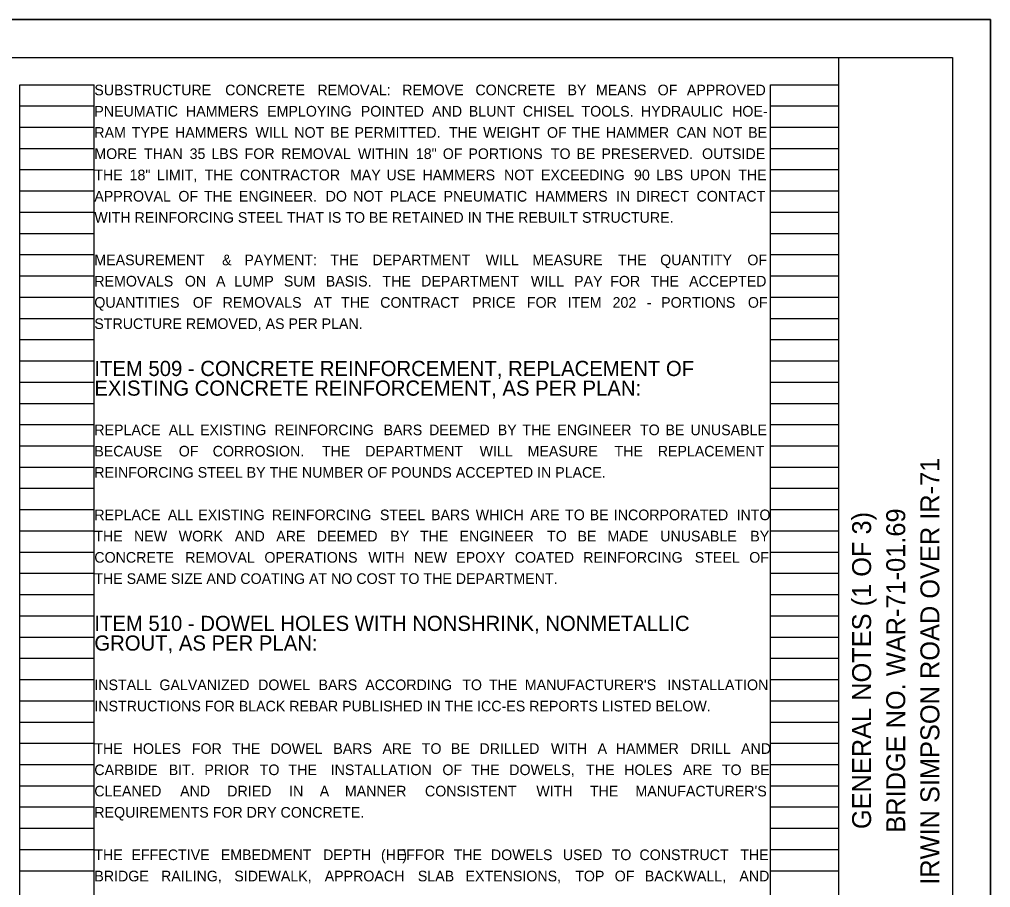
# Model space of a CAD drawing. Extents: x 0 to 34, y 0 to 22.
# Drawn here: x 21.2 to 34, y 10.56 to 22 of the extents above; entities that cross this region are included whole.
import ezdxf

# ---------------------------------------------------------------- set-up
doc = ezdxf.new("R2010")
doc.units = 0
for name, color, linetype in [('BR_P_Gen_Text', 7, 'Continuous'), ('Default', 7, 'Continuous'), ('SC_Scratch1', 7, 'Continuous'), ('SH_Border', 7, 'Continuous'), ('SH_Cut_Line', 7, 'Continuous'), ('SH_Data', 7, 'Continuous'), ('SH_Text', 7, 'Continuous')]:
    doc.layers.add(name, color=color, linetype=linetype)

msp = doc.modelspace()

# ---------------------------------------------------------------- linework, layer by layer
at = {"layer": 'SC_Scratch1'}
for p, q in [((21.207, 0.98), (21.207, 21.14)), ((21.207, 21.14), (22.187, 21.14)), ((22.187, 0.98), (22.187, 21.14)), ((31.1, 0.98), (31.1, 21.14)), ((31.1, 21.14), (32, 21.14)), ((32, 0.98), (32, 21.14)), ((21.207, 20.86), (22.187, 20.86)), ((31.1, 20.86), (32, 20.86)), ((21.207, 20.58), (22.187, 20.58)), ((31.1, 20.58), (32, 20.58)), ((21.207, 20.3), (22.187, 20.3)), ((31.1, 20.3), (32, 20.3)), ((21.207, 20.02), (22.187, 20.02)), ((31.1, 20.02), (32, 20.02)), ((21.207, 19.74), (22.187, 19.74)), ((31.1, 19.74), (32, 19.74)), ((21.207, 19.46), (22.187, 19.46)), ((31.1, 19.46), (32, 19.46)), ((21.207, 19.18), (22.187, 19.18)), ((31.1, 19.18), (32, 19.18)), ((21.207, 18.9), (22.187, 18.9)), ((31.1, 18.9), (32, 18.9)), ((21.207, 18.62), (22.187, 18.62)), ((31.1, 18.62), (32, 18.62)), ((21.207, 18.34), (22.187, 18.34)), ((31.1, 18.34), (32, 18.34)), ((21.207, 18.06), (22.187, 18.06)), ((31.1, 18.06), (32, 18.06)), ((21.207, 17.78), (22.187, 17.78)), ((31.1, 17.78), (32, 17.78)), ((21.207, 17.5), (22.187, 17.5)), ((31.1, 17.5), (32, 17.5)), ((21.207, 17.22), (22.187, 17.22)), ((31.1, 17.22), (32, 17.22)), ((21.207, 16.94), (22.187, 16.94)), ((31.1, 16.94), (32, 16.94)), ((21.207, 16.66), (22.187, 16.66)), ((31.1, 16.66), (32, 16.66)), ((21.207, 16.38), (22.187, 16.38)), ((31.1, 16.38), (32, 16.38)), ((21.207, 16.1), (22.187, 16.1)), ((31.1, 16.1), (32, 16.1)), ((21.207, 15.82), (22.187, 15.82)), ((31.1, 15.82), (32, 15.82)), ((21.207, 15.54), (22.187, 15.54)), ((31.1, 15.54), (32, 15.54)), ((21.207, 15.26), (22.187, 15.26)), ((31.1, 15.26), (32, 15.26)), ((21.207, 14.98), (22.187, 14.98)), ((31.1, 14.98), (32, 14.98)), ((21.207, 14.7), (22.187, 14.7)), ((31.1, 14.7), (32, 14.7)), ((21.207, 14.42), (22.187, 14.42)), ((31.1, 14.42), (32, 14.42)), ((21.207, 14.14), (22.187, 14.14)), ((31.1, 14.14), (32, 14.14)), ((21.207, 13.86), (22.187, 13.86)), ((31.1, 13.86), (32, 13.86)), ((21.207, 13.58), (22.187, 13.58)), ((31.1, 13.58), (32, 13.58)), ((21.207, 13.3), (22.187, 13.3)), ((31.1, 13.3), (32, 13.3)), ((21.207, 13.02), (22.187, 13.02)), ((31.1, 13.02), (32, 13.02)), ((21.207, 12.74), (22.187, 12.74)), ((31.1, 12.74), (32, 12.74)), ((21.207, 12.46), (22.187, 12.46)), ((31.1, 12.46), (32, 12.46)), ((21.207, 12.18), (22.187, 12.18)), ((31.1, 12.18), (32, 12.18)), ((21.207, 11.9), (22.187, 11.9)), ((31.1, 11.9), (32, 11.9)), ((21.207, 11.62), (22.187, 11.62)), ((31.1, 11.62), (32, 11.62)), ((21.207, 11.34), (22.187, 11.34)), ((31.1, 11.34), (32, 11.34)), ((21.207, 11.06), (22.187, 11.06)), ((31.1, 11.06), (32, 11.06)), ((21.207, 10.78), (22.187, 10.78)), ((31.1, 10.78), (32, 10.78))]:
    msp.add_line(p, q, dxfattribs=at)
msp.add_lwpolyline([(0, 22), (34, 22), (34, 0), (0, 0)], close=True, dxfattribs=at)
at = {"layer": 'SH_Border'}
msp.add_line((32, 0.5), (32, 21.5), dxfattribs=at)
msp.add_lwpolyline([(1.5, 21.5), (33.5, 21.5), (33.5, 0.5), (1.5, 0.5)], close=True, dxfattribs=at)
at = {"layer": 'SH_Cut_Line'}
msp.add_lwpolyline([(0, 0), (34, 0), (34, 22), (0, 22)], close=True, dxfattribs=at)

# ---------------------------------------------------------------- texts
at = {"layer": 'BR_P_Gen_Text'}
for s, p in [('ITEM 509 - CONCRETE REINFORCEMENT, REPLACEMENT OF ', (22.187, 17.3)), ('EXISTING CONCRETE REINFORCEMENT, AS PER PLAN: ', (22.187, 17.041)), ('ITEM 510 - DOWEL HOLES WITH NONSHRINK, NONMETALLIC ', (22.187, 13.94)), ('GROUT, AS PER PLAN:', (22.187, 13.681))]:
    msp.add_text(s, height=0.2, dxfattribs=at).set_placement(p)
at = {"layer": 'Default'}
for s, p in [('SUBSTRUCTURE ', (22.187, 21)), ('CONCRETE ', (23.912, 21)), ('REMOVAL: ', (25.127, 21)), ('REMOVE ', (26.245, 21)), ('CONCRETE ', (27.21, 21)), ('BY ', (28.424, 21)), ('MEANS ', (28.799, 21)), ('OF ', (29.612, 21)), ('APPROVED ', (29.997, 21)), ('PNEUMATIC ', (22.187, 20.72)), ('HAMMERS ', (23.395, 20.72)), ('EMPLOYING ', (24.465, 20.72)), ('POINTED ', (25.699, 20.72)), ('AND ', (26.639, 20.72)), ('BLUNT ', (27.122, 20.72)), ('CHISEL ', (27.834, 20.72)), ('TOOLS. ', (28.608, 20.72)), ('HYDRAULIC ', (29.392, 20.72)), ('HOE-', (30.593, 20.72)), ('RAM ', (22.187, 20.44)), ('TYPE ', (22.681, 20.44)), ('HAMMERS ', (23.251, 20.44)), ('WILL ', (24.311, 20.44)), ('NOT ', (24.823, 20.44)), ('BE ', (25.296, 20.44)), ('PERMITTED. ', (25.616, 20.44)), ('THE ', (26.86, 20.44)), ('WEIGHT ', (27.311, 20.44)), ('OF ', (28.153, 20.44)), ('THE ', (28.48, 20.44)), ('HAMMER ', (28.931, 20.44)), ('CAN ', (29.86, 20.44)), ('NOT ', (30.333, 20.44)), ('BE ', (30.805, 20.44)), ('MORE ', (22.187, 20.16)), ('THAN ', (22.842, 20.16)), ('35 ', (23.443, 20.16)), ('LBS ', (23.73, 20.16)), ('FOR ', (24.168, 20.16)), ('REMOVAL ', (24.65, 20.16)), ('WITHIN ', (25.661, 20.16)), ('18" ', (26.425, 20.16)), ('OF ', (26.78, 20.16)), ('PORTIONS ', (27.117, 20.16)), ('TO ', (28.204, 20.16)), ('BE ', (28.541, 20.16)), ('PRESERVED. ', (28.87, 20.16)), ('OUTSIDE ', (30.197, 20.16)), ('THE ', (22.187, 19.88)), ('18" ', (22.652, 19.88)), ('LIMIT, ', (23.013, 19.88)), ('THE ', (23.641, 19.88)), ('CONTRACTOR ', (24.106, 19.88)), ('MAY ', (25.557, 19.88)), ('USE ', (26.037, 19.88)), ('HAMMERS ', (26.513, 19.88)), ('NOT ', (27.587, 19.88)), ('EXCEEDING ', (28.074, 19.88)), ('90 ', (29.3, 19.88)), ('LBS ', (29.592, 19.88)), ('UPON ', (30.036, 19.88)), ('THE ', (30.675, 19.88)), ('APPROVAL ', (22.187, 19.6)), ('OF ', (23.295, 19.6)), ('THE ', (23.632, 19.6)), ('ENGINEER. ', (24.092, 19.6)), ('DO ', (25.236, 19.6)), ('NOT ', (25.598, 19.6)), ('PLACE ', (26.08, 19.6)), ('PNEUMATIC ', (26.79, 19.6)), ('HAMMERS ', (27.996, 19.6)), ('IN ', (29.064, 19.6)), ('DIRECT ', (29.328, 19.6)), ('CONTACT ', (30.125, 19.6)), ('WITH REINFORCING STEEL THAT IS TO BE RETAINED IN THE REBUILT STRUCTURE. ', (22.187, 19.32)), ('MEASUREMENT ', (22.187, 18.76)), ('& ', (23.871, 18.76)), ('PAYMENT: ', (24.165, 18.76)), ('THE ', (25.298, 18.76)), ('DEPARTMENT ', (25.853, 18.76)), ('WILL ', (27.345, 18.76)), ('MEASURE ', (27.961, 18.76)), ('THE ', (29.091, 18.76)), ('QUANTITY ', (29.645, 18.76)), ('OF ', (30.794, 18.76)), ('REMOVALS ', (22.187, 18.48)), ('ON ', (23.38, 18.48)), ('A ', (23.791, 18.48)), ('LUMP ', (24.032, 18.48)), ('SUM ', (24.685, 18.48)), ('BASIS. ', (25.237, 18.48)), ('THE ', (25.985, 18.48)), ('DEPARTMENT ', (26.494, 18.48)), ('WILL ', (27.941, 18.48)), ('PAY ', (28.511, 18.48)), ('FOR ', (28.987, 18.48)), ('THE ', (29.518, 18.48)), ('ACCEPTED ', (30.026, 18.48)), ('QUANTITIES ', (22.187, 18.2)), ('OF ', (23.485, 18.2)), ('REMOVALS ', (23.878, 18.2)), ('AT ', (25.079, 18.2)), ('THE ', (25.439, 18.2)), ('CONTRACT ', (25.955, 18.2)), ('PRICE ', (27.166, 18.2)), ('FOR ', (27.888, 18.2)), ('ITEM ', (28.426, 18.2)), ('202 ', (29.018, 18.2)), ('PORTIONS ', (29.658, 18.2)), ('OF ', (30.801, 18.2)), ('- ', (29.469, 18.2)), ('STRUCTURE REMOVED, AS PER PLAN. ', (22.187, 17.92))]:
    msp.add_text(s, height=0.14, dxfattribs=at).set_placement(p)
at = {"layer": 'SH_Data'}
for s, p in [('IRWIN SIMPSON ROAD OVER IR-71', (33.325, 10.595)), ('BRIDGE NO. WAR-71-01.69', (32.875, 11.282)), ('GENERAL NOTES (1 OF 3)', (32.425, 11.329))]:
    msp.add_text(s, height=0.25, rotation=90, dxfattribs=at).set_placement(p)
at = {"layer": 'SH_Text'}
for s, p in [('REPLACE ', (22.187, 16.52)), ('ALL ', (23.168, 16.52)), ('EXISTING ', (23.58, 16.52)), ('REINFORCING ', (24.561, 16.52)), ('BARS ', (25.999, 16.52)), ('DEEMED ', (26.599, 16.52)), ('BY ', (27.504, 16.52)), ('THE ', (27.83, 16.52)), ('ENGINEER ', (28.289, 16.52)), ('TO ', (29.379, 16.52)), ('BE ', (29.715, 16.52)), ('UNUSABLE ', (30.044, 16.52)), ('BECAUSE ', (22.187, 16.24)), ('OF ', (23.3, 16.24)), ('CORROSION. ', (23.747, 16.24)), ('THE ', (25.187, 16.24)), ('DEPARTMENT ', (25.757, 16.24)), ('WILL ', (27.265, 16.24)), ('MEASURE ', (27.897, 16.24)), ('THE ', (29.043, 16.24)), ('REPLACEMENT ', (29.613, 16.24)), ('REINFORCING STEEL BY THE NUMBER OF POUNDS ACCEPTED IN PLACE. ', (22.187, 15.96)), ('REPLACE ', (22.187, 15.4)), ('ALL ', (23.156, 15.4)), ('EXISTING ', (23.557, 15.4)), ('REINFORCING ', (24.527, 15.4)), ('STEEL ', (25.952, 15.4)), ('BARS ', (26.625, 15.4)), ('WHICH ', (27.214, 15.4)), ('ARE ', (27.933, 15.4)), ('TO ', (28.392, 15.4)), ('BE ', (28.716, 15.4)), ('INCORPORATED ', (29.034, 15.4)), ('INTO ', (30.652, 15.4)), ('THE ', (22.187, 15.12)), ('NEW ', (22.71, 15.12)), ('WORK ', (23.299, 15.12)), ('AND ', (24.039, 15.12)), ('ARE ', (24.585, 15.12)), ('DEEMED ', (25.119, 15.12)), ('BY ', (26.088, 15.12)), ('THE ', (26.478, 15.12)), ('ENGINEER ', (27.001, 15.12)), ('TO ', (28.155, 15.12)), ('BE ', (28.555, 15.12)), ('MADE ', (28.949, 15.12)), ('UNUSABLE ', (29.646, 15.12)), ('BY ', (30.833, 15.12)), ('CONCRETE ', (22.187, 14.84)), ('REMOVAL ', (23.386, 14.84)), ('OPERATIONS ', (24.429, 14.84)), ('WITH ', (25.799, 14.84)), ('NEW ', (26.399, 14.84)), ('EPOXY ', (26.957, 14.84)), ('COATED ', (27.729, 14.84)), ('REINFORCING ', (28.631, 14.84)), ('STEEL ', (30.101, 14.84)), ('OF ', (30.819, 14.84)), ('THE SAME SIZE AND COATING AT NO COST TO THE DEPARTMENT.', (22.187, 14.56)), ('INSTALL ', (22.187, 13.16)), ('GALVANIZED ', (23.045, 13.16)), ('DOWEL ', (24.346, 13.16)), ('BARS ', (25.142, 13.16)), ('ACCORDING ', (25.758, 13.16)), ('TO ', (27.036, 13.16)), ('THE ', (27.387, 13.16)), ("MANUFACTURER'S ", (27.861, 13.16)), ('INSTALLATION ', (29.739, 13.16)), ('INSTRUCTIONS FOR BLACK REBAR PUBLISHED IN THE ICC-ES REPORTS LISTED BELOW. ', (22.187, 12.88)), ('THE ', (22.187, 12.32)), ('HOLES ', (22.693, 12.32)), ('FOR ', (23.472, 12.32)), ('THE ', (24.001, 12.32)), ('DOWEL ', (24.508, 12.32)), ('BARS ', (25.337, 12.32)), ('ARE ', (25.985, 12.32)), ('TO ', (26.503, 12.32)), ('BE ', (26.887, 12.32)), ('DRILLED ', (27.263, 12.32)), ('WITH ', (28.205, 12.32)), ('A ', (28.82, 12.32)), ('HAMMER ', (29.059, 12.32)), ('DRILL ', (30.044, 12.32)), ('AND ', (30.711, 12.32)), ('CARBIDE ', (22.187, 12.04)), ('BIT. ', (23.167, 12.04)), ('PRIOR ', (23.637, 12.04)), ('TO ', (24.367, 12.04)), ('THE  ', (24.746, 12.04)), ('INSTALLATION ', (25.302, 12.04)), ('OF ', (26.775, 12.04)), ('THE ', (27.154, 12.04)), ('DOWELS, ', (27.656, 12.04)), ('THE ', (28.669, 12.04)), ('HOLES ', (29.171, 12.04)), ('ARE ', (29.945, 12.04)), ('TO ', (30.458, 12.04)), ('BE ', (30.837, 12.04)), ('CLEANED ', (22.187, 11.76)), ('AND ', (23.318, 11.76)), ('DRIED ', (23.939, 11.76)), ('IN ', (24.755, 11.76)), ('A ', (25.158, 11.76)), ('MANNER ', (25.489, 11.76)), ('CONSISTENT ', (26.545, 11.76)), ('WITH ', (28.013, 11.76)), ('THE ', (28.72, 11.76)), ("MANUFACTURER'S ", (29.319, 11.76)), ('REQUIREMENTS FOR DRY CONCRETE. ', (22.187, 11.48)), ('THE ', (22.187, 10.92)), ('EFFECTIVE ', (22.677, 10.92)), ('EMBEDMENT ', (23.853, 10.92)), ('DEPTH ', (25.202, 10.92)), ('(H', (25.965, 10.92)), ('EF', (26.171, 10.92)), (') ', (26.246, 10.92)), ('FOR ', (26.411, 10.92)), ('THE ', (26.923, 10.92)), ('DOWELS ', (27.414, 10.92)), ('USED ', (28.362, 10.92)), ('TO ', (29.005, 10.92)), ('CONSTRUCT ', (29.372, 10.92)), ('THE ', (30.7, 10.92)), ('BRIDGE ', (22.187, 10.64)), ('RAILING, ', (23.066, 10.64)), ('SIDEWALK, ', (24.032, 10.64)), ('APPROACH ', (25.223, 10.64)), ('SLAB ', (26.451, 10.64)), ('EXTENSIONS, ', (27.08, 10.64)), ('TOP ', (28.525, 10.64)), ('OF ', (29.046, 10.64)), ('BACKWALL, ', (29.443, 10.64)), ('AND ', (30.689, 10.64))]:
    msp.add_text(s, height=0.14, dxfattribs=at).set_placement(p)

doc.saveas('drawing.dxf')
